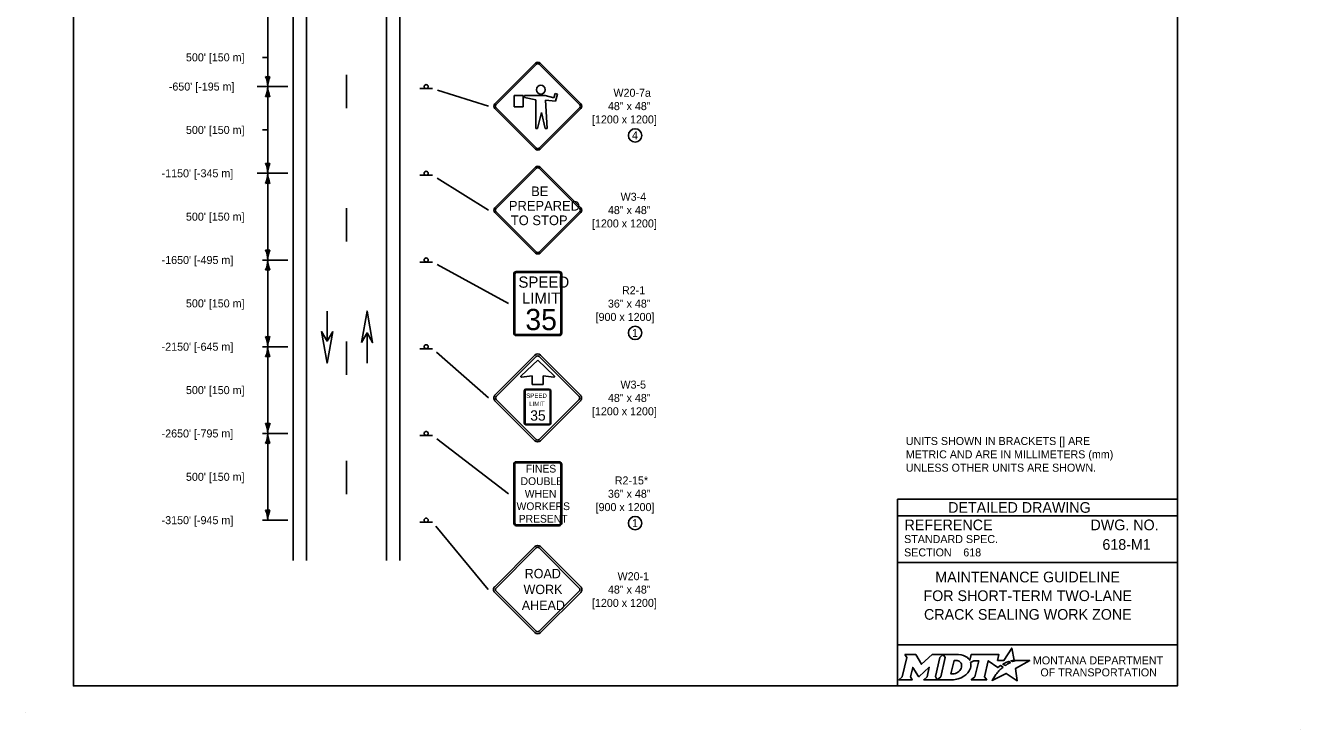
# Model space of a CAD drawing. Extents: x 49987.3 to 50021, y 49987.6 to 50011.4.
# Drawn here: x 49999.98 to 50009.54, y 49999.74 to 50005.01 of the extents above; entities that cross this region are included whole.
import ezdxf

# ---------------------------------------------------------------- set-up
doc = ezdxf.new("R2010")
doc.units = 0
for name, color, linetype in [('Default', 7, 'Continuous'), ('Level 1', 7, 'Continuous'), ('Level 2', 7, 'Continuous'), ('Level 3', 7, 'Continuous')]:
    doc.layers.add(name, color=color, linetype=linetype)

msp = doc.modelspace()

# ---------------------------------------------------------------- linework, layer by layer
at = {"layer": 'Default'}
for p, q in [((50001.7532, 50004.7735), (50001.7932, 50004.7735)), ((50001.7531, 50004.5545), (50001.7131, 50004.5545)), ((50001.7532, 50004.2295), (50001.7932, 50004.2295)), ((50001.7131, 50003.9045), (50001.7531, 50003.9045))]:
    msp.add_line(p, q, dxfattribs=at)
at = {"layer": 'Level 1'}
for p, q in [((50001.9831, 50001.0011), (50001.9831, 50007.6183)), ((50002.083, 50001.0011), (50002.0831, 50007.6183)), ((50002.683, 50001.0011), (50002.6831, 50007.6183)), ((50002.783, 50001.0011), (50002.783, 50007.6183)), ((50003.8008, 50004.7296), (50003.4967, 50004.4256)), ((50003.8078, 50004.7227), (50003.5038, 50004.4185)), ((50004.1329, 50004.4185), (50003.8291, 50004.7227)), ((50004.1401, 50004.4256), (50003.8361, 50004.7296)), ((50002.3831, 50004.3938), (50002.3831, 50004.6437)), ((50003.029, 50004.5393), (50002.9331, 50004.5393)), ((50003.6401, 50004.402), (50003.6401, 50004.4869)), ((50003.6401, 50004.4869), (50003.7095, 50004.4869)), ((50003.7095, 50004.4869), (50003.7095, 50004.402)), ((50003.8739, 50004.4865), (50003.7174, 50004.4865)), ((50003.7174, 50004.4865), (50003.7174, 50004.4725)), ((50003.7174, 50004.4725), (50003.8023, 50004.4557)), ((50003.8023, 50004.4557), (50003.8023, 50004.2391)), ((50003.9394, 50004.4713), (50003.8739, 50004.4865)), ((50003.8879, 50004.2391), (50003.8766, 50004.4536)), ((50003.8766, 50004.4536), (50003.9505, 50004.4452)), ((50003.9491, 50004.5014), (50003.9394, 50004.4713)), ((50003.9656, 50004.4971), (50003.9491, 50004.5014)), ((50003.9505, 50004.4452), (50003.9656, 50004.4971)), ((50003.4967, 50004.3904), (50003.8008, 50004.0864)), ((50003.5038, 50004.3974), (50003.8078, 50004.0934)), ((50003.7095, 50004.402), (50003.6401, 50004.402)), ((50003.8162, 50004.2391), (50003.8451, 50004.3612)), ((50003.8291, 50004.0934), (50004.1329, 50004.3974)), ((50003.8361, 50004.0864), (50004.1401, 50004.3904)), ((50003.8451, 50004.3612), (50003.8741, 50004.2391)), ((50003.8023, 50004.2391), (50003.8162, 50004.2391)), ((50003.8741, 50004.2391), (50003.8879, 50004.2391)), ((50003.029, 50003.8893), (50002.9331, 50003.8893)), ((50003.8008, 50003.9502), (50003.4967, 50003.6462)), ((50003.8078, 50003.9432), (50003.5038, 50003.6391)), ((50004.1329, 50003.6391), (50003.8291, 50003.9432)), ((50004.1401, 50003.6462), (50003.8361, 50003.9502)), ((50002.3831, 50003.3939), (50002.3831, 50003.6438)), ((50003.4967, 50003.6109), (50003.8008, 50003.3069)), ((50003.5038, 50003.6179), (50003.8078, 50003.3139)), ((50003.8291, 50003.3139), (50004.1329, 50003.6179)), ((50003.8361, 50003.3069), (50004.1401, 50003.6109)), ((50003.029, 50003.2393), (50002.9331, 50003.2393)), ((50003.6375, 50003.1479), (50003.6375, 50002.7079)), ((50003.6451, 50003.1479), (50003.6451, 50002.7079)), ((50003.9787, 50003.1679), (50003.6562, 50003.1679)), ((50003.9787, 50003.1599), (50003.6562, 50003.1599)), ((50003.99, 50002.7079), (50003.99, 50003.1479)), ((50003.9975, 50002.7079), (50003.9975, 50003.1479)), ((50002.2381, 50002.8722), (50002.2381, 50002.6463)), ((50002.2384, 50002.8722), (50002.2384, 50002.6463)), ((50002.3831, 50002.394), (50002.3831, 50002.6439)), ((50002.5378, 50002.4819), (50002.5378, 50002.708)), ((50002.5381, 50002.4819), (50002.5381, 50002.708)), ((50003.6562, 50002.696), (50003.9787, 50002.696)), ((50003.6562, 50002.688), (50003.9787, 50002.688)), ((50003.029, 50002.5894), (50002.9331, 50002.5894)), ((50003.7961, 50002.5414), (50003.4968, 50002.2421)), ((50003.8062, 50002.5313), (50003.5069, 50002.232)), ((50003.7961, 50002.5414), (50003.7961, 50002.5414)), ((50003.8062, 50002.5313), (50003.8062, 50002.5313)), ((50004.128, 50002.232), (50003.8287, 50002.5313)), ((50004.1381, 50002.2421), (50003.8388, 50002.5414)), ((50003.8175, 50002.5029), (50003.693, 50002.3856)), ((50003.9419, 50002.3856), (50003.8175, 50002.5029)), ((50003.6971, 50002.377), (50003.7771, 50002.387)), ((50003.7771, 50002.387), (50003.7771, 50002.3215)), ((50003.8578, 50002.3215), (50003.8578, 50002.387)), ((50003.8578, 50002.387), (50003.9378, 50002.377)), ((50003.7171, 50002.0326), (50003.7171, 50002.2739)), ((50003.7223, 50002.0326), (50003.7223, 50002.2739)), ((50003.7296, 50002.2864), (50003.9043, 50002.2864)), ((50003.7296, 50002.2812), (50003.9043, 50002.2812)), ((50003.7771, 50002.3215), (50003.8578, 50002.3215)), ((50003.8169, 50002.2864), (50003.8169, 50002.2864)), ((50003.9116, 50002.2739), (50003.9116, 50002.0326)), ((50003.9168, 50002.2739), (50003.9168, 50002.0326)), ((50003.4968, 50002.1993), (50003.7961, 50001.9)), ((50003.5069, 50002.2094), (50003.8062, 50001.9101)), ((50003.8287, 50001.9101), (50004.128, 50002.2094)), ((50003.8388, 50001.9), (50004.1381, 50002.1993)), ((50003.9043, 50002.0253), (50003.7296, 50002.0253)), ((50003.9043, 50002.0201), (50003.7296, 50002.0201)), ((50003.029, 50001.9393), (50002.9331, 50001.9393)), ((50002.3831, 50001.4997), (50002.3831, 50001.7497)), ((50003.6375, 50001.7225), (50003.6375, 50001.2825)), ((50003.6451, 50001.7225), (50003.6451, 50001.2825)), ((50003.9787, 50001.7426), (50003.6563, 50001.7426)), ((50003.9787, 50001.7346), (50003.6563, 50001.7346)), ((50003.99, 50001.2825), (50003.99, 50001.7225)), ((50003.9975, 50001.2825), (50003.9975, 50001.7225)), ((50003.029, 50001.2893), (50002.9331, 50001.2893)), ((50003.6563, 50001.2707), (50003.9787, 50001.2707)), ((50003.6563, 50001.2626), (50003.9787, 50001.2626)), ((50003.7962, 50001.1069), (50003.4953, 50000.8061)), ((50003.8062, 50001.0967), (50003.5055, 50000.796)), ((50003.7962, 50001.1069), (50003.7962, 50001.1069)), ((50003.8062, 50001.0967), (50003.8062, 50001.0967)), ((50004.1296, 50000.796), (50003.8289, 50001.0967)), ((50004.1398, 50000.8061), (50003.8391, 50001.1069)), ((50003.4953, 50000.7631), (50003.7962, 50000.4624)), ((50003.5055, 50000.7733), (50003.8062, 50000.4725)), ((50003.8176, 50000.7846), (50003.8176, 50000.7846)), ((50003.8176, 50000.7846), (50003.8176, 50000.7846)), ((50003.8176, 50000.7846), (50003.8176, 50000.7846)), ((50003.8289, 50000.4725), (50004.1296, 50000.7733)), ((50003.8391, 50000.4624), (50004.1398, 50000.7631)), ((49999.9766, 49999.8624), (49999.9766, 49999.8624)), ((50009.5374, 49999.7356), (50009.5374, 49999.7356))]:
    msp.add_line(p, q, dxfattribs=at)
for points in [[(50008.6146, 50011.2628), (50000.3356, 50011.2628), (50000.3356, 50000.0624), (50008.6146, 50000.0624)], [(50002.4961, 50002.6355), (50002.5378, 50002.8722), (50002.5797, 50002.6355), (50002.5378, 50002.7077)], [(50002.2802, 50002.7186), (50002.2384, 50002.4821), (50002.1966, 50002.7186), (50002.2384, 50002.6463)]]:
    msp.add_lwpolyline(points, close=True, dxfattribs=at)
for points in [[(50003.9489, 50004.5012), (50003.9491, 50004.5014)], [(50003.95, 50004.4453), (50003.9507, 50004.4461)], [(50003.7092, 50004.402), (50003.7095, 50004.4024)]]:
    msp.add_lwpolyline(points, dxfattribs=at)
for centre, radius in [((50002.981, 50004.5547), 0.0152), ((50003.8408, 50004.531), 0.0334), ((50002.981, 50003.9045), 0.0152), ((50002.981, 50003.2546), 0.0152), ((50002.981, 50002.6046), 0.0152), ((50002.981, 50001.9545), 0.0152), ((50002.981, 50001.3046), 0.0152)]:
    msp.add_circle(centre, radius, dxfattribs=at)
for centre, radius, start, end in [((50003.8184, 50004.7121), 0.025, 45, 135), ((50003.8184, 50004.7121), 0.015, 45, 135), ((50003.5144, 50004.4081), 0.025, 135, 225), ((50003.5144, 50004.4081), 0.015, 135, 225), ((50004.1224, 50004.4081), 0.015, 315, 45.00024), ((50004.1224, 50004.4081), 0.025, 315, 45.00024), ((50003.8184, 50004.104), 0.025, 225, 314.99957), ((50003.8184, 50004.104), 0.015, 225, 314.99957), ((50003.8184, 50003.9326), 0.025, 45, 135), ((50003.8184, 50003.9326), 0.015, 45, 135), ((50003.5144, 50003.6286), 0.025, 135, 225), ((50003.5144, 50003.6286), 0.015, 135, 225), ((50004.1224, 50003.6286), 0.015, 315, 45.00024), ((50004.1224, 50003.6286), 0.025, 315, 45.00024), ((50003.8184, 50003.3246), 0.025, 225, 314.99957), ((50003.8184, 50003.3246), 0.015, 225, 314.99957), ((50003.8175, 50002.52), 0.0302, 45.00007, 134.99993), ((50003.8175, 50002.52), 0.016, 45.00007, 134.99993), ((50003.6966, 50002.382), 0.00508, 134.62874, 275.82948), ((50003.9383, 50002.382), 0.00509, 264.38259, 45.16491), ((50003.5182, 50002.2207), 0.0302, 134.99993, 225.00008), ((50003.5182, 50002.2207), 0.016, 134.99993, 225.00008), ((50003.7296, 50002.2739), 0.0125, 90, 180), ((50003.7296, 50002.2739), 0.00728, 90, 180), ((50003.9043, 50002.2739), 0.0125, 360, 90), ((50003.9043, 50002.2739), 0.00728, 360, 90), ((50004.1168, 50002.2207), 0.016, 314.99993, 45.00007), ((50004.1168, 50002.2207), 0.0302, 314.99993, 45.00008), ((50003.7296, 50002.0326), 0.0125, 180, 270), ((50003.7296, 50002.0326), 0.00728, 180, 270), ((50003.9043, 50002.0326), 0.00728, 270, 360), ((50003.9043, 50002.0326), 0.0125, 270, 360), ((50003.8175, 50001.9214), 0.0302, 225.00007, 314.99993), ((50003.8175, 50001.9214), 0.016, 225.00007, 314.99993), ((50003.8175, 50001.0852), 0.0304, 45.00008, 134.99993), ((50003.8175, 50001.0852), 0.016, 45.00008, 134.99993), ((50003.5167, 50000.7845), 0.0304, 134.99993, 225.00008), ((50004.1182, 50000.7845), 0.0304, 314.99993, 45.00008), ((50003.5167, 50000.7845), 0.016, 134.99993, 225.00008), ((50004.1182, 50000.7845), 0.016, 314.99993, 45.00007), ((50003.8175, 50000.4837), 0.0304, 225.00007, 314.99993), ((50003.8175, 50000.4837), 0.016, 225.00007, 314.99993)]:
    msp.add_arc(centre, radius, start, end, dxfattribs=at)
for centre, major_axis, start_param, end_param in [((50003.6564, 50003.148), (0, 0.02), 0, 1.570796), ((50003.6564, 50003.148), (0, 0.012), 0, 1.570796), ((50003.9789, 50003.148), (0, 0.02), 4.712389, 6.283185), ((50003.9789, 50003.148), (0, 0.012), 4.712389, 6.283185), ((50003.6564, 50002.7081), (0, -0.02), 4.712389, 6.283185), ((50003.6564, 50002.7081), (0, -0.012), 4.712389, 6.283185), ((50003.9789, 50002.7081), (0, -0.02), 0, 1.570796), ((50003.9789, 50002.7081), (0, -0.012), 0, 1.570796), ((50003.6562, 50001.7227), (0, 0.02), 0, 1.570796), ((50003.6562, 50001.7227), (0, 0.012), 0, 1.570796), ((50003.9787, 50001.7227), (0, 0.02), 4.712389, 6.283185), ((50003.9787, 50001.7227), (0, 0.012), 4.712389, 6.283185), ((50003.6562, 50001.2827), (0, -0.02), 4.712389, 6.283185), ((50003.6562, 50001.2827), (0, -0.012), 4.712389, 6.283185), ((50003.9787, 50001.2827), (0, -0.02), 0, 1.570796), ((50003.9787, 50001.2827), (0, -0.012), 0, 1.570796)]:
    msp.add_ellipse(centre, major_axis=major_axis, ratio=0.9375, start_param=start_param, end_param=end_param, dxfattribs=at)
at = {"layer": 'Level 2'}
for p, q in [((50008.6146, 50001.4624), (50006.5146, 50001.4624)), ((50006.5146, 50001.4624), (50006.5146, 50000.0624)), ((50008.6146, 50001.3374), (50006.5146, 50001.3374)), ((50008.2507, 50001.1223), (50008.2507, 50001.1223)), ((50007.0089, 50001.0629), (50007.0089, 50001.0629)), ((50008.6146, 50000.9874), (50006.5146, 50000.9874)), ((50007.5646, 50000.7383), (50007.5646, 50000.7383)), ((50008.6146, 50000.3693), (50006.5146, 50000.3693))]:
    msp.add_line(p, q, dxfattribs=at)
for points in [[(50007.3771, 50000.2447), (50007.3668, 50000.2503), (50007.3784, 50000.2531), (50007.39, 50000.2551), (50007.3726, 50000.3452), (50007.3131, 50000.2539), (50007.2658, 50000.2532), (50007.2761, 50000.2973), (50007.0669, 50000.2974), (50007.0568, 50000.2549), (50007.051, 50000.2632)], [(50006.5701, 50000.2974), (50006.5842, 50000.274), (50006.5507, 50000.1307), (50006.525, 50000.1082), (50006.6266, 50000.1082), (50006.6131, 50000.131), (50006.6293, 50000.2011), (50006.673, 50000.1321), (50006.6783, 50000.1321), (50006.7534, 50000.2016), (50006.737, 50000.1305), (50006.7123, 50000.1085), (50006.8139, 50000.1085), (50006.8001, 50000.1318), (50006.8333, 50000.2742)], [(50006.8333, 50000.2742), (50006.8586, 50000.2974), (50006.7762, 50000.2974), (50006.6966, 50000.2244), (50006.6521, 50000.2971), (50006.5701, 50000.2974)], [(50006.9722, 50000.2974), (50006.8586, 50000.2974), (50006.8733, 50000.2745), (50006.8394, 50000.1307), (50006.8139, 50000.1085), (50006.9245, 50000.1085)], [(50006.9962, 50000.2107), (50006.995, 50000.2026), (50006.9918, 50000.1933), (50006.9876, 50000.1851), (50006.982, 50000.1776), (50006.9755, 50000.1707), (50006.9676, 50000.1644), (50006.9593, 50000.1597), (50006.9502, 50000.1558), (50006.9411, 50000.1535), (50006.9319, 50000.1526), (50006.916, 50000.1526), (50006.9396, 50000.2526), (50006.9556, 50000.2526), (50006.9632, 50000.252), (50006.9708, 50000.2501), (50006.9774, 50000.2471), (50006.9835, 50000.2429), (50006.9883, 50000.2379), (50006.992, 50000.2319), (50006.9947, 50000.2257), (50006.9963, 50000.2183), (50006.9963, 50000.2153), (50006.9962, 50000.2107)], [(50007.0636, 50000.2383), (50007.0882, 50000.2514), (50007.1251, 50000.2514), (50007.0965, 50000.1309), (50007.069, 50000.1082), (50007.1852, 50000.1082), (50007.1682, 50000.1311), (50007.1964, 50000.2513), (50007.2677, 50000.1996), (50007.2888, 50000.2147), (50007.3085, 50000.2038)], [(50007.2527, 50000.1479), (50007.2374, 50000.1235), (50007.2327, 50000.116), (50007.2269, 50000.1074), (50007.2246, 50000.1031), (50007.3299, 50000.1562), (50007.4138, 50000.1011), (50007.4007, 50000.1938), (50007.5076, 50000.2522), (50007.4583, 50000.253), (50007.4282, 50000.2534), (50007.4074, 50000.2537), (50007.4006, 50000.2522), (50007.3957, 50000.251), (50007.3873, 50000.2487), (50007.3771, 50000.2447)], [(50007.3267, 50000.2171), (50007.3243, 50000.2154), (50007.306, 50000.225), (50007.3163, 50000.2307), (50007.3204, 50000.2329), (50007.329, 50000.2369), (50007.3347, 50000.2395), (50007.3426, 50000.2425), (50007.3499, 50000.2452), (50007.3617, 50000.2378), (50007.3577, 50000.2357), (50007.3531, 50000.2332), (50007.3489, 50000.231), (50007.3439, 50000.2281), (50007.342, 50000.227), (50007.3393, 50000.2254), (50007.3368, 50000.224), (50007.3345, 50000.2224), (50007.3319, 50000.2206), (50007.3292, 50000.2188), (50007.3267, 50000.2171)], [(50006.9702, 50000.1158), (50006.9786, 50000.1184), (50006.9916, 50000.1238), (50007.012, 50000.1348)], [(50007.2666, 50000.164), (50007.2666, 50000.164)]]:
    msp.add_lwpolyline(points, dxfattribs=at)
for centre in [(50004.5478, 50004.1881), (50004.5477, 50002.708), (50004.5477, 50001.2825)]:
    msp.add_circle(centre, 0.05, dxfattribs=at)
for centre, radius, start, end in [((50006.9953, 50000.219), 0.0709, 339.53292, 15.85821), ((50006.9513, 50000.2363), 0.1183, 300.91025, 339.13831)]:
    msp.add_arc(centre, radius, start, end, dxfattribs=at)
for centre, major_axis, ratio, start_param, end_param in [((50006.9701, 50000.25), (0.0834, -0.0037), 0.568097, 0.61298, 1.570796), ((50007.0257, 50000.2573), (0.0361, -0.0295), 0.469099, 1.225588, 1.570796), ((50007.2597, 50000.1559), (-0.00694, -0.00806), 0.008222, 0, 3.137361), ((50007.2764, 50000.1742), (-0.0098, -0.0102), 0.016458, 3.141593, 6.279097), ((50007.2974, 50000.1941), (-0.0112, -0.0097), 0.021651, 3.157348, 6.283185), ((50006.9248, 50000.2568), (0, 0.1484), 0.987302, 3.139398, 3.456847)]:
    msp.add_ellipse(centre, major_axis=major_axis, ratio=ratio, start_param=start_param, end_param=end_param, dxfattribs=at)
at = {"layer": 'Level 3'}
for p, q in [((50001.7932, 50001.3045), (50001.7932, 50005.2045)), ((50001.7531, 50004.5545), (50001.9432, 50004.5545)), ((50003.0671, 50004.5274), (50003.4494, 50004.4081)), ((50001.7531, 50003.9045), (50001.9431, 50003.9045)), ((50003.063, 50003.8682), (50003.4494, 50003.6286)), ((50001.7532, 50003.2545), (50001.9431, 50003.2545)), ((50003.064, 50003.2201), (50003.5975, 50002.9279)), ((50001.7531, 50002.6045), (50001.9431, 50002.6045)), ((50003.059, 50002.563), (50003.4479, 50002.2207)), ((50001.7531, 50001.9545), (50001.9431, 50001.9545)), ((50003.0607, 50001.915), (50003.5975, 50001.5025)), ((50001.7532, 50001.3045), (50001.9431, 50001.3045)), ((50003.0545, 50001.2585), (50003.4463, 50000.7845))]:
    msp.add_line(p, q, dxfattribs=at)
for centre, radius, start, end in [((50001.7932, 50004.6827), 0.0548, 252.13882, 287.86118), ((50001.5605, 50004.543), 0.233, 2.82731, 22.07716), ((50002.0153, 50004.5454), 0.2223, 157.45601, 177.63952), ((50001.5711, 50004.5637), 0.2223, 337.45601, 357.63952), ((50002.0259, 50004.566), 0.233, 182.82731, 202.07716), ((50001.7932, 50004.4263), 0.0548, 72.13882, 107.86118), ((50001.7932, 50004.0327), 0.0548, 252.13882, 287.86118), ((50001.5605, 50003.893), 0.233, 2.82731, 22.07716), ((50002.0153, 50003.8954), 0.2223, 157.45601, 177.63952), ((50001.5711, 50003.9137), 0.2223, 337.45601, 357.63952), ((50002.0259, 50003.916), 0.233, 182.82731, 202.07716), ((50001.7932, 50003.7763), 0.0548, 72.13882, 107.86118), ((50001.7932, 50003.3827), 0.0548, 252.14219, 287.86455), ((50001.5605, 50003.243), 0.233, 2.83068, 22.08053), ((50002.0153, 50003.2454), 0.2223, 157.45938, 177.64289), ((50001.571, 50003.2636), 0.2223, 337.47849, 357.662), ((50002.0259, 50003.2661), 0.233, 182.84979, 202.09964), ((50001.7932, 50003.1263), 0.0548, 72.1613, 107.88366), ((50001.7931, 50002.7327), 0.0548, 252.1613, 287.88366), ((50001.5605, 50002.5929), 0.233, 2.84979, 22.09964), ((50002.0153, 50002.5954), 0.2223, 157.47849, 177.662), ((50001.5711, 50002.6138), 0.2223, 337.43016, 357.61366), ((50001.7931, 50002.4763), 0.0548, 72.11296, 107.83532), ((50002.0259, 50002.6159), 0.233, 182.80146, 202.05131), ((50001.7932, 50002.0827), 0.0548, 252.11296, 287.83532), ((50001.5605, 50001.9431), 0.233, 2.80146, 22.05131), ((50001.571, 50001.9637), 0.2223, 337.45938, 357.64289), ((50002.0153, 50001.9453), 0.2223, 157.43016, 177.61366), ((50002.0259, 50001.966), 0.233, 182.83068, 202.08053), ((50001.7932, 50001.8263), 0.0548, 72.14219, 107.86455), ((50001.7932, 50001.4327), 0.0548, 252.14219, 287.86455), ((50001.5605, 50001.293), 0.233, 2.83068, 22.08053), ((50002.0153, 50001.2954), 0.2223, 157.45938, 177.64289)]:
    msp.add_arc(centre, radius, start, end, dxfattribs=at)

# ---------------------------------------------------------------- texts
at = {"layer": 'Level 1'}
for s, height, p in [('BE', 0.07249, (50003.7682, 50003.7333)), ('PREPARED', 0.07249, (50003.6013, 50003.6247)), ('TO STOP', 0.07249, (50003.616, 50003.5158)), ('SPEED', 0.08409, (50003.6727, 50003.0469)), ('LIMIT', 0.08409, (50003.6993, 50002.9268)), ('35', 0.15912, (50003.7248, 50002.729)), ('FINES', 0.05799, (50003.7278, 50001.6617)), ('DOUBLE', 0.05799, (50003.6891, 50001.5678)), ('WHEN', 0.05799, (50003.7206, 50001.4739)), ('WORKERS', 0.05799, (50003.659, 50001.38)), ('PRESENT', 0.05799, (50003.675, 50001.2861)), ('ROAD', 0.07021, (50003.7197, 50000.8692)), ('WORK', 0.07021, (50003.7111, 50000.7504)), ('AHEAD', 0.07021, (50003.698, 50000.6317))]:
    msp.add_text(s, height=height, dxfattribs=at).set_placement(p)
for s, height, p in [('SPEED', 0.03301, (50003.7316, 50002.2207)), ('LIMIT', 0.03301, (50003.7535, 50002.1597)), ('35', 0.07775, (50003.7615, 50002.0503))]:
    msp.add_text(s, height=height, rotation=360, dxfattribs=at).set_placement(p)
at = {"layer": 'Level 2'}
for s, height, p in [("500' [150 m]", 0.059993, (50001.1799, 50004.7435)), ("-650' [-195 m]", 0.059993, (50001.0513, 50004.5245)), ('W20-7a', 0.05999, (50004.3854, 50004.478)), ('48" x 48"', 0.05999, (50004.344, 50004.3781)), ('[1200 x 1200]', 0.059993, (50004.2246, 50004.2781)), ("500' [150 m]", 0.059993, (50001.1799, 50004.1995)), ('4', 0.06, (50004.5241, 50004.1583)), ("-1150' [-345 m]", 0.059993, (50000.9974, 50003.8745)), ('W3-4', 0.05999, (50004.439, 50003.6986)), ("500' [150 m]", 0.059993, (50001.1799, 50003.5495)), ('48" x 48"', 0.05999, (50004.344, 50003.5986)), ('[1200 x 1200]', 0.059993, (50004.2246, 50003.4986)), ("-1650' [-495 m]", 0.059993, (50000.9975, 50003.2245)), ('R2-1', 0.05999, (50004.4495, 50002.9979)), ("500' [150 m]", 0.059993, (50001.1799, 50002.8995)), ('36" x 48"', 0.05999, (50004.344, 50002.8979)), ('[900 x 1200]', 0.059993, (50004.2515, 50002.798)), ('1', 0.06, (50004.525, 50002.678)), ("-2150' [-645 m]", 0.059993, (50000.9975, 50002.5745)), ('W3-5', 0.05999, (50004.438, 50002.2907)), ("500' [150 m]", 0.059993, (50001.1799, 50002.2495)), ('48" x 48"', 0.05999, (50004.344, 50002.1907)), ('[1200 x 1200]', 0.059993, (50004.2246, 50002.0907)), ("-2650' [-795 m]", 0.059993, (50000.9974, 50001.9245)), ('UNITS SHOWN IN BRACKETS [] ARE ', 0.06, (50006.5779, 50001.868)), ('METRIC AND ARE IN MILLIMETERS (mm) ', 0.06, (50006.5779, 50001.768)), ("500' [150 m]", 0.059993, (50001.1799, 50001.5995)), ('UNLESS OTHER UNITS ARE SHOWN.', 0.06, (50006.5779, 50001.668)), ('R2-15*', 0.05999, (50004.3955, 50001.5725)), ('36" x 48"', 0.05999, (50004.344, 50001.4725)), ('[900 x 1200]', 0.059993, (50004.2515, 50001.3725)), ('DETAILED DRAWING', 0.0799, (50006.8956, 50001.3599)), ("-3150' [-945 m]", 0.059993, (50000.9975, 50001.2745)), ('1', 0.06, (50004.525, 50001.2525)), ('REFERENCE', 0.08, (50006.5682, 50001.229)), ('DWG. NO.', 0.08, (50007.9624, 50001.229)), ('STANDARD SPEC.', 0.06, (50006.5649, 50001.133)), ('SECTION', 0.06, (50006.5649, 50001.033)), ('618', 0.06, (50007.0089, 50001.0329)), ('618-M1', 0.08, (50008.0519, 50001.0823)), ('W20-1', 0.05999, (50004.4163, 50000.8545)), ('MAINTENANCE GUIDELINE', 0.08, (50006.7987, 50000.8383)), ('48" x 48"', 0.05999, (50004.344, 50000.7545)), ('[1200 x 1200]', 0.059993, (50004.2246, 50000.6545)), ('FOR SHORT-TERM TWO-LANE', 0.08, (50006.7102, 50000.6983)), ('CRACK SEALING WORK ZONE', 0.08, (50006.7143, 50000.5583)), ('MONTANA DEPARTMENT', 0.06, (50007.5308, 50000.2236)), ('OF TRANSPORTATION', 0.06, (50007.587, 50000.1336))]:
    msp.add_text(s, height=height, dxfattribs=at).set_placement(p)

doc.saveas('drawing.dxf')
